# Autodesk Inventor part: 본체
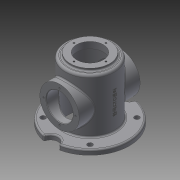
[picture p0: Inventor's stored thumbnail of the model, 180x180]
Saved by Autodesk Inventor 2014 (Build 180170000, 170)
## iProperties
Created: 2018-04
Part Number: 본체
Material: Generic
Document SubType Name: Modeling
Designer: kb542
Density: 1 g/cm^3
Appearance: Default
Mass: 424.919 g
Surface Area: 1201.34 cm^2
Volume: 424.919 cm^3
Author: kb542
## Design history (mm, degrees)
sketch "스케치1"
  geometry: L1 (0, 0)-(0, 133); L2 (27, 133)-(40, 133); L3 (40, 133)-(40, 128); L4 (40, 128)-(50, 128); L5 (50, 128)-(50, 18); L6 (50, 18)-(80, 18); L7 (80, 18)-(80, 8); L8 (80, 8)-(50, 8); L9 (50, 8)-(50, 0); L10 (50, 0)-(45, 0); L11 (45, 0)-(45, 120); L12 (45, 120)-(27, 120); L13 (27, 120)-(27, 133)
  constraints: 26 end point, 10 parallel, 2 horizontal alignment, 2 perpendicular, 1 vertical, 1 vertical alignment
  dimensions: "d0" = 133 distance of L1.start L1.end; "d1" = 8 distance between parallel lines of L10 L8; "d2" = 13 distance between parallel lines of L12 L2; "d3" = 10 distance between parallel lines of L8 L6; "d4" = 54 diameter of L13 L1; "d5" = 80 diameter of L3 L1; "d6" = 110 distance between parallel lines of L6 L4; "d7" = 90 diameter of L11 L1; "d8" = 100 diameter of L9 L1; "d10" = 160 diameter of L7 L1
revolve "회전1" sketch "스케치1" stored, may be unused: angle "d9" = 90 deg
node "작업 평면1"
sketch "스케치2"
  geometry: L1 (-50, 0)-(50, 0) reference; L2 (-80, 8)-(80, 8) reference; C1 r 27 at (0, 68); C2 r 40 at (0, 68); 1 further point
  constraints: 2 centre point, 1 coincident, 1 vertical alignment
  dimensions: "d13" = 80 diameter of C2; "d14" = 54 diameter of C1; "d45" = 60 distance from line of L2 C1.centre
extrude "돌출1" join sketch "스케치2" stored distance "d15" = 10; taper "d16" = 0 deg
extrude "돌출2" cut sketch "스케치2" stored distance "d17" = 10; taper "d18" = 0 deg
sketch "스케치5"
  geometry: C1 r 27 at (0, 0) reference; C2 r 40 at (0, 0) reference; A1 r 32.5 centre (0, 0) between (0, 32.5) and (-32.5, 0); 3 further points
  constraints: 4 point on circle, 2 horizontal alignment, 2 vertical alignment, 1 centre point, 1 coincident
  dimensions: "d27" = 65 diameter of A1
hole "구멍1" sketch "스케치5" at (0, 32.5), (-32.5, 0), (32.5, 0), (0, -32.5) diameter "d28" = 3.242; stored, may be unused: countersink angle "d32" = 90 deg, drill point angle "d34" = 118 deg; dims "d29" = 8, "d30" = 4, "d31" = 2, "d33" = 10
sketch "스케치6"
  geometry: C1 r 40 at (0, 0) reference; C2 r 27 at (0, 0) reference; A1 r 32.5 centre (0, 0) between (0, 32.5) and (-32.5, 0); 2 further points
  constraints: 4 point on circle, 2 horizontal alignment, 2 vertical alignment, 1 centre point, 1 coincident
  dimensions: "d35" = 65 diameter of A1
hole "구멍2" sketch "스케치6" at (0, 32.5), (-32.5, 0), (0, -32.5), (32.5, 0) diameter "d36" = 3.242; stored, may be unused: countersink angle "d40" = 90 deg, drill point angle "d42" = 118 deg; dims "d37" = 8, "d38" = 4, "d39" = 2, "d41" = 10
node "작업 평면2"
sketch "스케치3"
  geometry: 2 further points
  constraints: 1 horizontal alignment, 1 other
  dimensions: "d19" = 70 distance of point (-73, 0) point (-3, 0)
feature "엠보싱1" sketch "스케치3" dims "d20" = 0.5, "d21" = 0
sketch "스케치4"
  geometry: L1 (0, 0)-(67.5, 0); L2 (0, 0)-(47.73, 47.73); C1 r 15 at (0, 80); C2 r 15 at (0, -80); C3 r 5 at (47.73, 47.73); C4 r 5 at (-47.73, 47.73); C5 r 5 at (-47.73, -47.73); C6 r 5 at (47.73, -47.73); A1 r 80 centre (0, 0) between (0, 80) and (0, -80); A2 r 67.5 centre (0, 0) between (67.5, 0) and (47.73, 47.73); 1 further point
  constraints: 8 centre point, 4 end point, 4 point on circle, 3 coincident, 2 vertical alignment, 1 equal radius, 1 horizontal, 9 other
  dimensions: "d23" = 30 diameter of C1; "d24" = 160 diameter of A1; "d46" = 135 diameter of A2; "d47" = 45 deg angle of L1 L2; "d48" = 10 diameter of C3; "d51" = 360 deg dimension on L1.start C3.centre (derived)
extrude "돌출3" cut sketch "스케치4" stored distance "d25" = 11; taper "d26" = 0 deg
fillet "모깎기1" dims "d22" = 5, "d43" = 3
fillet "모깎기2" dims "d44" = 3
chamfer "모따기1" distance "d53" = 1; stored, may be unused: second distance "d54" = 2, angle "d55" = 45 deg
node "솔리드1"
mirror "대칭1"
other parameters: "d11" = 62
